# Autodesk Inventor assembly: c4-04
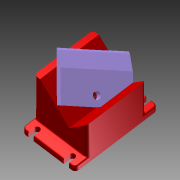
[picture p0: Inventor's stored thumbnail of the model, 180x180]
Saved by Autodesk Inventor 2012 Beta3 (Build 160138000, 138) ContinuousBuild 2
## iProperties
Created: 2010-11
Part Number: c4-04
Document SubType Name: Assembly
Designer: Beta-8540w
Author: Beta-8540w
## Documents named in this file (3)
- C:\Inventor 2012 Essentials\Assemblies\Chapter 4\c4-04.iam
- C:\Inventor 2012 Essentials\Parts\Chapter 4\c4-03.ipt
- C:\Inventor 2012 Essentials\Parts\Chapter 4\c4-04.ipt
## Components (2 placed, 2 different names)
1. c4-03:1 — Insert:1
2. c4-04:1 — Insert:1
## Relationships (1: Insert 1)
- Insert:1: c4-03:1 ↔ c4-04:1
